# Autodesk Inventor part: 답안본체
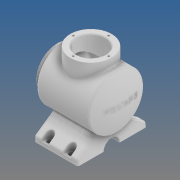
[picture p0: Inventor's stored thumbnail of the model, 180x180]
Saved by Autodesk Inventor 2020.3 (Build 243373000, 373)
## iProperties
Created: 2021-04
Part Number: 답안본체
Material: 알루미늄 6061
Document SubType Name: Modeling
Designer: EZDESIGN
Density: 2.7 g/cm^3
Appearance: 기본값
Mass: 1685.26 g
Surface Area: 1049.95 cm^2
Volume: 624.172 cm^3
Author: EZDESIGN
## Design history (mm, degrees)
sketch "스케치1"
  geometry: L1 (15, 50)-(106.454, 50); L2 (0, 0)-(120, 0); L3 (0, 27)-(22, 27); L4 (22, 27)-(22, 37); L5 (25, 40)-(99.903, 40); L6 (12, 47)-(12, 41); L7 (9, 38)-(0, 38); L8 (0, 38)-(0, 27); A1 r 113 centre (7, 0) between (120, 0) and (109.166, 48.282); A2 r 103 centre (7, 0) between (110, 0) and (102.69, 38.11); A3 r 3 centre (15, 47) between (15, 50) and (12, 47); A4 r 3 centre (9, 41) between (9, 38) and (12, 41); A5 r 3 centre (25, 37) between (25, 40) and (22, 37); A6 r 3 centre (99.903, 37) between (102.69, 38.11) and (99.903, 40); A7 r 3 centre (106.454, 47) between (109.166, 48.282) and (106.454, 50); 5 further points
  constraints: 16 end point, 16 point on circle, 10 point on line, 10 tangent, 7 centre point, 5 perpendicular, 2 equal radius, 1 horizontal, 1 other
  dimensions: "d0" = 120 distance of L2.start L2.end; "d13" = 226 diameter of A1; "d15" = 108 horizontal distance of L2.end point (12, 50); "d16" = 10 radial gap between concentric circles of A1 A2; "d17" = 22 distance of L3.start L3.end; "d18" = 54 diameter of L3 L2; "d19" = 100 diameter of L1 L2; "d20" = 12 distance of point (12, 38) L7.end; "d21" = 76 diameter of L7 L2; "d139" = 3 radius of A3; "d140" = 3 radius of A5 (derived); "d141" = 3 radius of A7 (derived)
revolve "회전2" sketch "스케치1" stored, may be unused: angle "d23" = 90 deg
node "작업 평면1"
sketch "스케치2"
  geometry: L1 (9.266, -30.075)-(62, -67); L2 (62, -67)-(62, -77); L3 (62, -77)-(15, -77); L4 (-9.266, -30.075)-(-62, -67); L5 (-62, -67)-(-62, -77); L6 (-62, -77)-(-15, -77); L7 (0, 0)-(0, -27); L8 (9.266, -30.075)-(-9.266, -30.075); C1 r 50 at (0, 0) reference; A1 r 15 centre (0, -77) between (15, -77) and (-15, -77); 4 further points
  constraints: 16 end point, 2 perpendicular, 2 point on circle, 2 point on line, 2 vertical, 2 vertical alignment, 1 centre point, 1 horizontal, 1 other
  dimensions: "d25" = 30 diameter of A1; "d26" = 124 distance between parallel lines of L5 L2; "d27" = 10 distance of L4.end L5.end; "d28" = 10 distance of L1.end L2.end; "d29" = 62 horizontal distance of L5.end point (0, 0); "d30" = 55 deg angle of L2 L1; "d31" = 55 deg angle of L5 L4; "d32" = 77 distance from line of L6 point (0, 0); "d33" = 15 distance edge to line of A1 L6; "d41" = 35.30635 distance from line of point (26.694, -42.278) L2; "d42" = 0 distance from line of point (26.694, -42.278) L1; "d43" = 88.69365 distance from line of point (-26.694, -42.278) L2; "d45" = 46.92509 distance between parallel lines of L8 L3; "d46" = 30.6217 distance from line of point (-26.694, -42.278) L1
extrude "돌출2" join sketch "스케치2" distance "d47" = 80; taper "d48" = 0 deg
node "작업 평면2"
sketch "스케치8"
  geometry: C1 r 38 at (42, -15); 1 further point
  constraints: 1 centre point, 1 horizontal alignment
  dimensions: "d79" = 76 diameter of C1; "d80" = 62 distance of point (-20, -15) C1.centre
extrude "돌출4" join sketch "스케치8" stored distance "d81" = 142; taper "d82" = 0 deg
sketch "스케치9"
  geometry: C1 r 38 at (0, 0) reference; C2 r 27 at (0, 0); 1 further point
  constraints: 1 centre point, 1 coincident
  dimensions: "d83" = 54 diameter of C2
extrude "돌출5" cut sketch "스케치9" distance "d84" = 50; taper "d85" = 0 deg
sketch "스케치10"
  geometry: C1 r 27 at (0, 0) reference; C2 r 38 at (0, 0) reference; A1 r 32.5 centre (0, 0) between (0, 32.5) and (-32.5, 0); 3 further points
  constraints: 4 point on circle, 2 horizontal alignment, 2 vertical alignment, 1 centre point, 1 coincident
  dimensions: "d86" = 65 diameter of A1
hole "구멍2" sketch "스케치10" at (0, 32.5), (-32.5, 0), (0, -32.5), (32.5, 0) diameter "d87" = 3.242; stored, may be unused: countersink angle "d91" = 90 deg, drill point angle "d93" = 118 deg; dims "d88" = 8, "d89" = 4, "d90" = 2, "d92" = 10
sketch "스케치11"
  geometry: C1 r 27 at (0, 0) reference; C2 r 38 at (0, 0) reference; A1 r 32.5 centre (0, 0) between (0, 32.5) and (-32.5, 0); 3 further points
  constraints: 4 point on circle, 2 horizontal alignment, 2 vertical alignment, 1 centre point, 1 coincident
  dimensions: "d94" = 65 diameter of A1
hole "구멍3" sketch "스케치11" at (0, 32.5), (-32.5, 0), (0, -32.5), (32.5, 0) diameter "d95" = 3.242; stored, may be unused: countersink angle "d99" = 90 deg, drill point angle "d101" = 118 deg; dims "d96" = 8, "d97" = 4, "d98" = 2, "d100" = 10
node "작업 평면4"
sketch "스케치14"
  geometry: L1 (0, 47)-(80, 47) reference; L2 (80, 47)-(80, 0) reference; L3 (13, 39)-(13, 47); L4 (27, 39)-(27, 47); L5 (53, 39)-(53, 47); L6 (67, 39)-(67, 47); L7 (0, -77)-(80, -77) reference; L8 (80, -30)-(80, -77) reference; L9 (13, -69)-(13, -77); L10 (27, -69)-(27, -77); L11 (53, -69)-(53, -77); L12 (67, -69)-(67, -77); A1 r 7 centre (20, 39) between (13, 39) and (27, 39); A2 r 7 centre (60, 39) between (53, 39) and (67, 39); A3 r 7 centre (20, -69) between (13, -69) and (27, -69); A4 r 7 centre (60, -69) between (53, -69) and (67, -69); 1 further point
  constraints: 16 end point, 8 perpendicular, 8 point on circle, 8 point on line, 8 tangent, 4 centre point, 1 horizontal alignment
  dimensions: "d112" = 14 diameter of A2; "d113" = 14 diameter of A1; "d114" = 8 distance from line of L1 A1.centre; "d115" = 8 distance from line of L1 A2.centre; "d116" = 20 distance from line of L2 A2.centre; "d117" = 40 distance of A2.centre A1.centre; "d120" = 14 diameter of A3; "d121" = 14 diameter of A4; "d122" = 8 distance from line of L7 A3.centre; "d123" = 20 distance from line of L8 A4.centre; "d124" = 40 distance of A3.centre A4.centre
extrude "돌출6" cut sketch "스케치14" distance "d118" = 40 (= d124); taper "d119" = 0 deg
sketch "스케치15"
  geometry: L1 (0, 1.252)-(80, 1.252) reference; L2 (80, 1.252)-(80, -47) reference; L3 (80, -47)-(67, -47) reference; L4 (67, -47)-(67, -39) reference; L5 (53, -39)-(53, -47) reference; L6 (53, -47)-(27, -47) reference; L7 (27, -47)-(13, -47) reference; L8 (13, -47)-(0, -47) reference; L9 (0, -47)-(0, 1.252) reference; L10 (67, -47)-(53, -47) reference; L11 (27, -47)-(27, -39) reference; L12 (13, -39)-(13, -47) reference; L13 (80, 28.748)-(0, 28.748) reference; L14 (0, 28.748)-(0, 77) reference; L15 (0, 77)-(13, 77) reference; L16 (13, 77)-(13, 69) reference; L17 (27, 69)-(27, 77) reference; L18 (27, 77)-(53, 77) reference; L19 (53, 77)-(67, 77) reference; L20 (67, 77)-(80, 77) reference; L21 (80, 77)-(80, 28.748) reference; L22 (13, 77)-(27, 77) reference; L23 (53, 77)-(53, 69) reference; L24 (67, 69)-(67, 77) reference; C1 r 4.5 at (20, -39); C2 r 4.5 at (60, -39); C3 r 4.5 at (60, 69); C4 r 4.5 at (20, 69); A1 r 7 centre (60, -39) between (67, -39) and (53, -39) reference; A2 r 7 centre (20, -39) between (27, -39) and (13, -39) reference; A3 r 7 centre (20, 69) between (13, 69) and (27, 69) reference; A4 r 7 centre (60, 69) between (53, 69) and (67, 69) reference; 1 further point
  constraints: 4 centre point, 4 coincident
  dimensions: "d125" = 9 diameter of C1; "d126" = 9 diameter of C2; "d127" = 9 diameter of C3; "d128" = 9 diameter of C4
extrude "돌출7" cut sketch "스케치15" distance "d129" = 10; taper "d130" = 0 deg
fillet "모깎기1" dims "d132" = 3
chamfer "모따기1" distance "d133" = 1; stored, may be unused: second distance "d134" = 2, angle "d135" = 45 deg
chamfer "모따기2" distance "d136" = 1; stored, may be unused: second distance "d137" = 2, angle "d138" = 45 deg
fillet "모깎기2" dims "d142" = 3
fillet "모깎기3" dims "d143" = 3
node "작업 평면8"
sketch "스케치20"
  geometry: 2 further points
  constraints: 1 coincident, 1 other
feature "엠보싱1" sketch "스케치20" dims "d0" = 120, "d13" = 226, "d15" = 108, "d16" = 10, "d17" = 22, "d18" = 54, "d19" = 100, "d20" = 12, "d21" = 76, "d25" = 30, "d26" = 124, "d27" = 10, "d28" = 10, "d29" = 62, "d30" = 55 deg, "d31" = 55 deg, "d32" = 77, "d33" = 15, "d41" = 35.30635, "d42" = 0, "d43" = 88.69365, "d45" = 46.92509, "d46" = 30.6217, "d139" = 3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
node "솔리드2"
node "절단 모서리 투영1"
node "절단 모서리 투영7"
node "절단 모서리 투영8"
node "절단 모서리 투영9"
node "절단 모서리 투영12"
feature "A9D066F2-1C7D-4E18-AEED-F7BC21143FA4" dims "d87" = 3.242, "d88" = 8, "d89" = 4, "d90" = 2, "d91" = 90 deg, "d92" = 10, "d93" = 118 deg
other parameters: "d78" = -142, "d107" = -6, "d145" = -174.25
